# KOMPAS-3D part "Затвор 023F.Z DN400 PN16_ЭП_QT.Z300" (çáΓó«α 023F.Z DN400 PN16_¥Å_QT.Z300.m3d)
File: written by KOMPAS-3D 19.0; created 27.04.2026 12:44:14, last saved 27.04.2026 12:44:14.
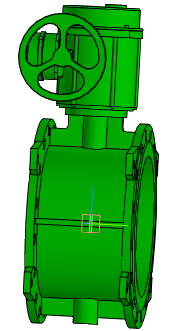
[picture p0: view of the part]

Document properties: Полное имя файла: Затвор 023F.Z DN400 PN16 +  электропривод QT.Z300.a3d

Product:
- Part/product: Затвор 023F.Z DN400 PN16_ЭП_QT.Z300
    Масса: 273.878
  - Body: Тело 1
      Масса: 274.394

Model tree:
1. Операция без истории:1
